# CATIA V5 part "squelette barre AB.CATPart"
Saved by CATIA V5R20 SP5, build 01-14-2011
Part number: squelette barre AB
Publications: "Point.3", "Point.1", "Droite.2"
Bounding box of the stored display mesh (mm): x 0 to 20, y 0 to 0, z 0 to 200
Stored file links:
  F:\projet\yyang_IAO\squelette barre AB.CATPart
  F:\projet\yyang_IAO\iao.CATProduct
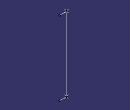
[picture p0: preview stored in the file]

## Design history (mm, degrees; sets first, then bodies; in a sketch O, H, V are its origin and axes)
External parameters (linked from other documents)
  `External.Longueur de barre AB et BC` = 200 mm
Set1
  Plane1: linked copy from another document
  Point1: linked copy from another document
Body1 (main body)
  Plane2: type Offset, RefPlane Plane1, Offset 0
  Point2: (0, 0, 0), relative to Point1
  Line1: type PtDir, RefPoint Point1, Direction (1, 0, 0), Start 0, End 20
  Point3: (0, 0, 200 {= `External.Longueur de barre AB et BC`}), relative to Point1
  Line2: type PtPt, FirstPoint Point1, SecondPoint Point3
  Line3: type PtDir, RefPoint Point3, Direction (1, 0, 0), Start 0, End 20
